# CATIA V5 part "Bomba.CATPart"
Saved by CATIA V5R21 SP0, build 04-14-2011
Part number: Bomba
Bounding box of the stored display mesh (mm): x -82.5 to 82.5, y -30 to 30, z -30 to 30
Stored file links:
  C:\Users\rodri\OneDrive\Área de Trabalho\FACULDADE\3°semestre\Sistemas Aeroespaciais\Projeto de avião 2019-02\CAD\Bomba.CATPart
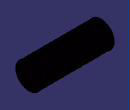
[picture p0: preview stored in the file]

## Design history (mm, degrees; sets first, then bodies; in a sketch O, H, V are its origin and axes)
Body1 (main body)
  Sketch1 on yz-plane, origin (0, 0, 0), H (0, 1, 0), V (0, 0, 1)
    circle A1 centre (0, 0) radius 30
    radius A1 = 30
  Pad1: profile Sketch1, direction (1, 0, 0), length 82.5, mirrored extent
